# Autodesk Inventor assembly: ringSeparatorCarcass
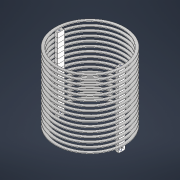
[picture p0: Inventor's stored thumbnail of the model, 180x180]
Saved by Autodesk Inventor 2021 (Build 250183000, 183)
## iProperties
Created: 2021-02
Part Number: ringSeparatorCarcass
Document SubType Name: Assembly
Designer: ftrauzettel
Author: ftrauzettel
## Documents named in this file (5)
- C:\Users\ftrauzettel\OneDrive\Delft\CPMM\Machined_Prototype\Mods\Assemblies\subAssemblies\ringSeparatorCarcass.iam
- C:\Users\ftrauzettel\OneDrive\Delft\CPMM\Machined_Prototype\Mods\Parts\original parts\Reading ring carcas part 1.ipt
- C:\Users\ftrauzettel\OneDrive\Delft\CPMM\Machined_Prototype\Mods\Parts\original parts\casing_reading_coupling.ipt
- C:\Users\ftrauzettel\OneDrive\Delft\CPMM\Machined_Prototype\Mods\Parts\original parts\pin through carcass.ipt
- C:\Users\ftrauzettel\OneDrive\Delft\CPMM\Machined_Prototype\Mods\Parts\original parts\Ring inbetween.ipt
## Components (20 placed, 4 different names)
1. casing_reading_coupling:1 — Mate:1, Flush:2, Mate:4
2. casing_reading_coupling:2 — Mate:2, Mate:3, Flush:1
3. pin through carcass:1 — Mate:6, Flush:3, Flush:4
4. pin through carcass:2 — Mate:5, Flush:3, Flush:5
5. Ring inbetween:1 — Mate:7, Mate:8
6. Reading ring carcas part 1:1 — Mate:1, Mate:2, Mate:3, Flush:1, Flush:2, Mate:4
7. Reading ring carcas part 1:2
8. Reading ring carcas part 1:3
9. Reading ring carcas part 1:4
10. Reading ring carcas part 1:5
11. Reading ring carcas part 1:6
12. Reading ring carcas part 1:7
13. Reading ring carcas part 1:8
14. Reading ring carcas part 1:9
15. Reading ring carcas part 1:10
16. Reading ring carcas part 1:11
17. Reading ring carcas part 1:12
18. Reading ring carcas part 1:13
19. Reading ring carcas part 1:14
20. Reading ring carcas part 1:15 — Mate:5, Mate:6, Flush:4, Flush:5, Mate:7, Mate:8
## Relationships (13: Mate 8, Flush 5)
- Mate:1: casing_reading_coupling:1 ↔ Reading ring carcas part 1:1
- Mate:2: casing_reading_coupling:2 ↔ Reading ring carcas part 1:1
- Mate:3: casing_reading_coupling:2 ↔ Reading ring carcas part 1:1
- Flush:1: casing_reading_coupling:2 ↔ Reading ring carcas part 1:1
- Flush:2: casing_reading_coupling:1 ↔ Reading ring carcas part 1:1
- Mate:4: casing_reading_coupling:1 ↔ Reading ring carcas part 1:1
- Mate:5: pin through carcass:2 ↔ Reading ring carcas part 1:15
- Mate:6: pin through carcass:1 ↔ Reading ring carcas part 1:15
- Flush:3: pin through carcass:1 ↔ pin through carcass:2
- Flush:4: pin through carcass:1 ↔ Reading ring carcas part 1:15
- Flush:5: pin through carcass:2 ↔ Reading ring carcas part 1:15
- Mate:7: Ring inbetween:1 ↔ Reading ring carcas part 1:15
- Mate:8: Ring inbetween:1 ↔ Reading ring carcas part 1:15
